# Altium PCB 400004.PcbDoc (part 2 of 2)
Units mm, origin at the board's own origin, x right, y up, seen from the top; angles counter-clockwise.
Board outline 80 x 40 mm, 4 copper layers (Top Layer, Mid-Layer 1, Mid-Layer 2, Bottom Layer), stack 1.582 mm thick; 116 components, 104 nets, 453 pads, 327 vias.
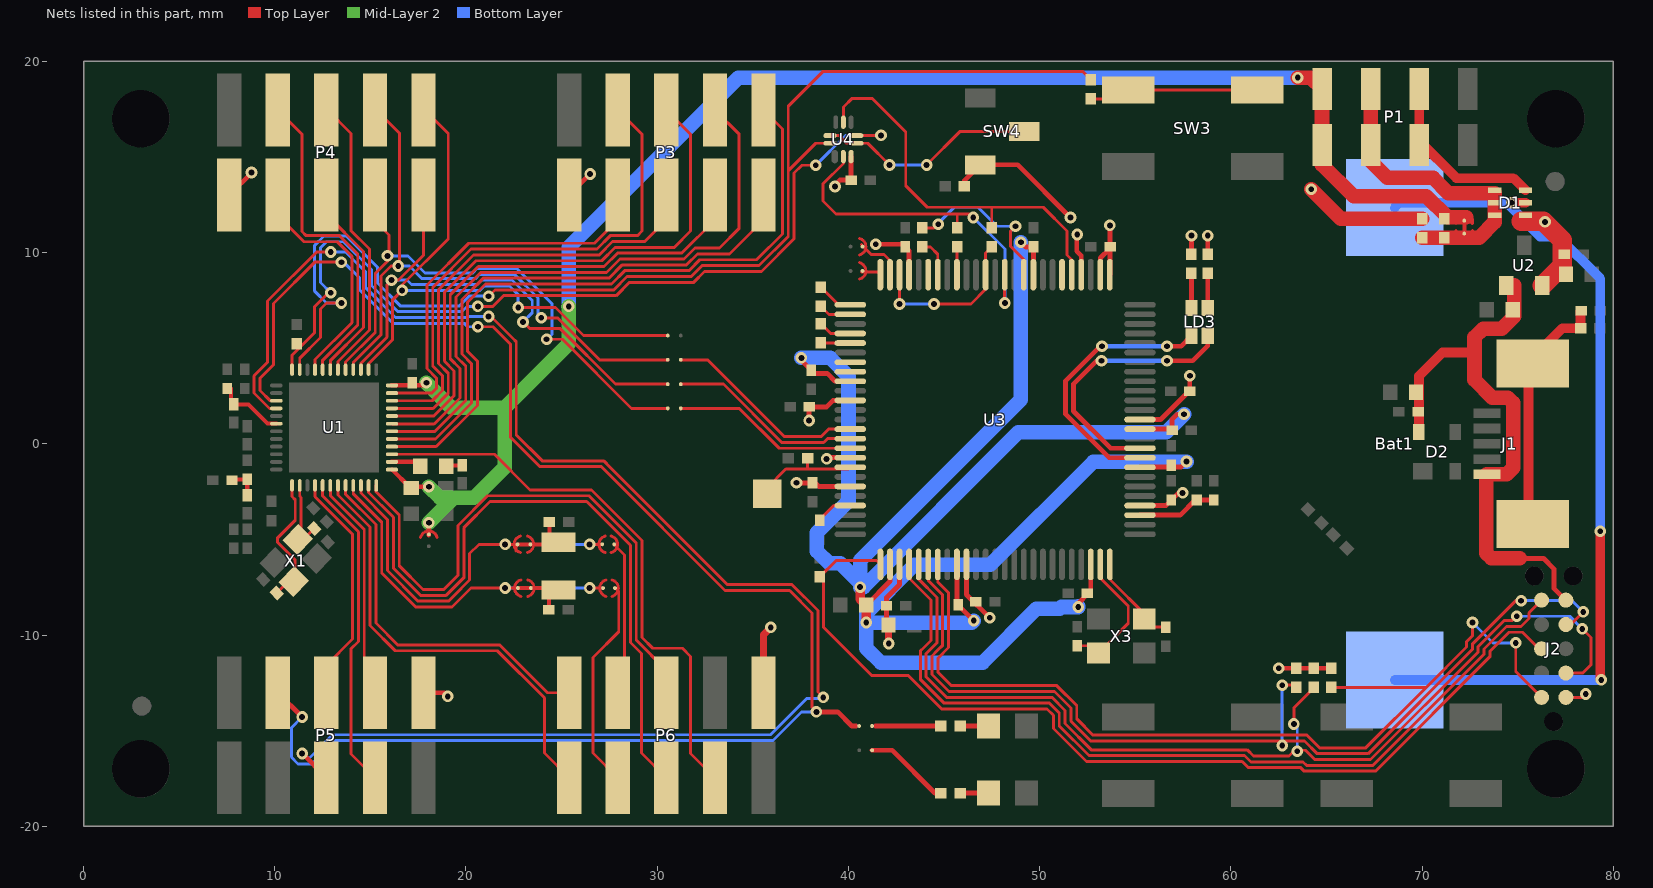
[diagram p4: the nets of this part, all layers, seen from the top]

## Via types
v1: diameter 0.61, hole 0.305, Top Layer to Bottom Layer, tented both sides, 311 vias
v2: diameter 0.66, hole 0.33, Top Layer to Bottom Layer, tented both sides, 16 vias

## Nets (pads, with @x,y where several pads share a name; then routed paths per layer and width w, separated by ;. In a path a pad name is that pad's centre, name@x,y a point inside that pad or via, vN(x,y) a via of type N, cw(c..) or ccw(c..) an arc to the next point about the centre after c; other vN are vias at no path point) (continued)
LED1: P5.4 SB7.1 U1.27 | length 86.3
  Top Layer w0.152: U1.27@10.106,2.253 9.761,2.253 9.223,2.791 9.223,3.429 9.931,4.137 9.931,7.339 12.092,9.5 v1(13.487,9.5) ; v1(20.625,6.121) 21.413,6.121 22.327,5.208 22.327,4.048 22.327,0.339 23.86,-1.194 27.077,-1.194 33.554,-7.671 36.93,-7.671 38.1,-8.841 38.1,-10.182 ; 38.1,-10.182 38.1,-13.792 v1(38.329,-14.021)
  Top Layer w0.254: P5.4@10.16,-13.018 v1(11.43,-14.287) ; v1(38.329,-14.021) 39.446,-14.021 40.183,-14.757 40.392,-14.757
  Bottom Layer w0.152: v1(11.43,-14.287) 10.871,-14.846 10.871,-16.388 11.222,-16.739 11.937,-16.739 13.156,-15.519 36.052,-15.519 37.55,-14.021 v1(38.329,-14.021) ; v1(13.487,9.5) 13.614,9.5 14.427,8.687 14.427,8.059 16.183,6.303 19.915,6.303 20.097,6.121 v1(20.625,6.121)
NetBat1_1: Bat1.1 D1.5 | length 45
  Top Layer w0.508: v1(74.691,12.609) D1.5@75.412,12.609 ; v1@79.324,-12.344 v1(79.324,-4.572)
  Bottom Layer w0.508: Bat1.1@68.572,-12.35 v1@79.324,-12.35 ; Bat1.1@68.572,12.35 68.831,12.609 74.412,12.609 76.175,10.846 77.114,10.846 79.324,8.636 v1(79.324,-4.572)
  other v1: 79.375,-12.344
NetC4_1: C4.1 C5.2 L3.1 | length 1.7
  Top Layer w0.229: C4.1@7.688,-1.864 C5.2@8.552,-1.864 ; L3.1@8.56,-2.685 C5.2@8.56,-1.856
NetC13_1: C13.1 SB2.1 X2.1 | length 2.6
  Top Layer w0.203: SB2.1@23.416,-7.544 23.503,-7.544 ; 23.568,-7.544 24.734,-7.544 24.341,-7.937 C13.1@24.341,-8.687
NetC14_1: C14.1 SB3.1 X2.2 | length 2.6
  Top Layer w0.203: SB3.1@23.391,-5.258 23.478,-5.258 ; 23.543,-5.258 24.734,-5.258 24.367,-4.89 C14.1@24.367,-4.089
NetC21_2: C21.2 J1.6 R9.2 | length 12.6
  Top Layer w0.508: J1.6@75.565,-3.965 75.565,3.965 J1.6@75.8,4.2 75.8,4.51 77.335,6.045 R9.2@78.291,6.045 C21.2@78.291,6.934
NetC31_2: C31.2 R12.2 U3.78 | length 4.1
  Top Layer w0.254: U3.78@55.251,-3.73 57.349,-3.73 58.141,-2.938 C31.2@59.03,-2.938
NetC32_2: C32.2 U3.47 | length 1.9
  Top Layer w0.152: C32.2@38.506,-3.962 39.239,-3.23 U3.47@40.101,-3.23
NetD1_6: D1.6 P1.3 | length 9.3
  Top Layer w0.508: P1.3@69.85,18.559 69.85,15.85 71.806,13.894 74.777,13.894 75.402,13.269 D1.6@75.412,13.269
NetL4_1: L4.1 U1.2 | length 1.6
  Top Layer w0.229: U1.2@16.106,-0.947 17.421,-0.947 L4.1@17.602,-1.128
NetL4_2: L4.2 L5.1 | length 0.8
  Top Layer w0.229: L4.2@18.982,-1.136 L5.1@19.786,-1.136
NetLD1_2: LD1.2 R5.1 | length 1.5
  Top Layer w0.254: R5.1@45.839,-18.263 LD1.2@47.327,-18.263
NetLD2_2: LD2.2 R6.1 | length 1.5
  Top Layer w0.254: R6.1@45.839,-14.757 LD2.2@47.327,-14.757
NetLD3_1: LD3.1 R23.1 | length 1.8
  Top Layer w0.254: LD3.1@58.794,7.1 R23.1@58.794,8.923
NetLD3_2: LD3.2 R22.1 | length 1.8
  Top Layer w0.254: LD3.2@57.944,7.1 R22.1@57.944,8.923
NetR3_1: R3.1 SW3.1 | length 8.9
  Top Layer w0.152: R3.1@52.68,18.042 53.653,18.042 54.121,18.51 SW3.1@61.389,18.51
NetR5_2: R5.2 SB6.2 | length 4.5
  Top Layer w0.254: SB6.2@41.239,-16.027 42.291,-16.027 44.526,-18.263 R5.2@44.839,-18.263
NetR6_2: R6.2 SB7.2 | length 3.4
  Top Layer w0.254: 41.411,-14.757 R6.2@44.839,-14.757
NetR18_2: R18.2 TP1.1 U3.43 | length 5.7
  Top Layer w0.152: TP1.1@35.763,-2.616 35.763,-2.286 36.728,-1.321 37.871,-1.321 ; R18.2@37.863,-0.762 37.863,-1.313 37.871,-1.321 ; U3.43@40.101,-1.23 40.01,-1.321 37.871,-1.321
NetSB17_1: SB17.1 U3.25 | length 1.1
  Top Layer w0.152: SB17.1@40.683,8.993 41.528,8.993 U3.25@41.676,8.845
NetSB18_1: SB18.1 U3.24 | length 2.6
  Top Layer w0.152: 40.682,10.414 41.197,9.899 41.867,9.899 42.176,9.589 U3.24@42.176,8.845
OB_LED1: LD3.4 U3.84 | length 14.1
  Top Layer w0.254: v1(53.264,5.105) 53.174,5.105 51.359,3.29 51.359,1.549 53.638,-0.73 U3.84@55.251,-0.73 ; v1(56.667,5.105) 57.399,5.105 LD3.4@57.944,5.65
  Bottom Layer w0.254: v1(53.264,5.105) v1(56.667,5.105)
OB_LED2: LD3.3 U3.85 | length 14.1
  Top Layer w0.254: v1(53.238,4.343) 52.987,4.343 51.765,3.122 51.765,1.718 53.713,-0.23 U3.85@55.251,-0.23 ; v1(56.667,4.343) 58.014,4.343 58.794,5.124 LD3.3@58.794,5.65
  Bottom Layer w0.254: v1(53.238,4.343) v1(56.667,4.343)
P0.00: P3.1 U1.4 | length 35.8
  Top Layer w0.152: U1.4@16.131,-0.147 18.442,-0.147 20.599,2.01 20.599,4.318 20.091,4.826 20.091,7.422 21.026,8.357 27.605,8.357 28.303,9.055 31.659,9.055 32.23,9.627 35.202,9.627 36.551,10.976 36.551,16.472 P3.1@35.56,17.463
P0.01: P3.2 U1.5 | length 29.4
  Top Layer w0.152: U1.5@16.131,0.253 18.411,0.253 20.295,2.137 20.295,4.192 19.787,4.7 19.787,7.548 20.9,8.661 27.478,8.661 28.177,9.36 31.533,9.36 32.104,9.931 33.782,9.931 35.56,11.709 P3.2@35.56,13.018
P0.02: P3.3 U1.6 | length 33.2
  Top Layer w0.152: U1.6@16.131,0.653 18.38,0.653 19.99,2.263 19.99,4.066 19.482,4.573 19.482,7.675 20.773,8.966 27.352,8.966 28.051,9.665 31.406,9.665 31.978,10.236 33.256,10.236 34.29,11.27 34.29,16.193 P3.3@33.02,17.463
P0.03: P3.4 U1.7 | length 26.5
  Top Layer w0.152: U1.7@16.131,1.053 16.143,1.041 18.337,1.041 19.685,2.389 19.685,3.939 19.177,4.447 19.177,7.801 20.647,9.271 27.226,9.271 27.924,9.97 31.28,9.97 33.02,11.709 P3.4@33.02,13.018
P0.04: P3.5 U1.8 | length 30.4
  Top Layer w0.152: U1.8@16.131,1.453 18.318,1.453 19.38,2.515 19.38,3.813 18.872,4.321 18.872,7.927 20.521,9.576 27.1,9.576 27.798,10.274 30.899,10.274 31.75,11.125 31.75,16.193 P3.5@30.48,17.463
P0.05: P3.6 U1.9 | length 23.6
  Top Layer w0.152: U1.9@16.131,1.853 18.287,1.853 19.075,2.642 19.075,3.687 18.567,4.195 18.567,8.053 20.395,9.881 26.973,9.881 27.672,10.579 29.35,10.579 30.48,11.709 P3.6@30.48,13.018
P0.06: P3.7 U1.10 | length 27.5
  Top Layer w0.152: U1.10@16.131,2.253 18.243,2.253 18.771,2.781 18.771,3.56 18.263,4.068 18.263,8.18 20.268,10.185 26.847,10.185 27.546,10.884 28.969,10.884 29.21,11.125 29.21,16.193 P3.7@27.94,17.463
P0.07: P3.8 U1.11 | length 20.8
  Top Layer w0.152: U1.11@16.106,2.653 18.212,2.653 18.466,2.907 18.466,3.434 17.958,3.942 17.958,8.306 20.142,10.49 26.721,10.49 27.94,11.709 P3.8@27.94,13.018
P0.08: P4.1 SB9.2 U1.14 | length 31.3
  Top Layer w0.152: U1.14@14.906,3.878 14.906,4.188 16.169,5.451 16.169,7.533 v1(16.662,8.026) 16.662,8.306 19.075,10.719 19.075,16.231 P4.1@17.805,17.501 ; v1(22.733,7.132) 24.676,7.132 26.146,5.662 SB9.2@30.557,5.662
  Bottom Layer w0.152: v1(16.662,8.026) 20.734,8.026 20.963,8.255 22.278,8.255 22.733,7.8 v1(22.733,7.132)
P0.09: P4.2 SB11.2 U1.15 | length 28.9
  Top Layer w0.152: U1.15@14.506,3.878 14.506,4.219 15.865,5.577 15.865,8.321 v1(16.104,8.56) 16.477,8.56 17.78,9.863 P4.2@17.78,13.018 ; v1(22.987,6.37) 23.317,6.04 24.906,6.04 27.824,3.122 SB11.2@30.557,3.122
  Bottom Layer w0.152: v1(16.104,8.56) 16.916,8.56 17.145,8.331 20.608,8.331 20.836,8.56 22.404,8.56 23.47,7.494 ; v1(22.987,6.37) 23.47,6.853 23.47,7.49
P0.10: P4.3 SB10.2 U1.16 | length 32.2
  Top Layer w0.152: U1.16@14.106,3.878 14.106,4.25 15.56,5.703 15.56,8.77 16.086,9.296 v1(16.459,9.296) 16.535,9.373 16.535,16.231 P4.3@15.265,17.501 ; v1(23.94,6.59) 24.787,6.59 26.985,4.392 SB10.2@30.557,4.392
  Bottom Layer w0.152: v1(16.459,9.296) 17.043,9.296 17.704,8.636 20.482,8.636 20.71,8.865 22.531,8.865 23.774,7.621 23.774,6.766 v1@23.94,6.6
P0.11: P4.4 SB12.2 U1.17 | length 29.8
  Top Layer w0.152: U1.17@13.706,3.878 13.706,4.281 15.255,5.829 15.255,8.905 v1@15.977,9.627 ; P4.4@15.24,13.018 15.24,11.659 15.977,10.922 v1@15.977,9.83 ; v1(24.22,5.47) 25.045,5.47 28.663,1.852 SB12.2@30.557,1.852
  Bottom Layer w0.152: v1(15.9,9.83) 16.967,9.83 17.856,8.941 20.355,8.941 20.584,9.169 22.657,9.169 24.5,7.326 24.5,5.72 v1@24.23,5.45
P0.12: P4.5 U1.18 | length 15.2
  Top Layer w0.152: P4.5@12.725,17.501 13.995,16.231 13.995,11.138 14.95,10.183 14.95,5.956 13.306,4.312 U1.18@13.306,3.878
P0.13: P4.6 U1.19 | length 10.7
  Top Layer w0.152: P4.6@12.725,13.056 12.725,11.977 14.645,10.057 14.645,6.082 12.906,4.343 U1.19@12.906,3.878
P0.14: P4.7 U1.20 | length 17.1
  Top Layer w0.152: P4.7@10.16,17.463 11.43,16.193 11.43,11.1 11.646,10.884 13.387,10.884 14.341,9.931 14.341,6.208 12.506,4.374 U1.20@12.506,3.878
P0.15: P4.8 U1.21 | length 12.6
  Top Layer w0.152: P4.8@10.16,13.018 10.16,11.939 11.532,10.566 13.274,10.566 14.036,9.804 14.036,6.334 12.106,4.405 U1.21@12.106,3.878
P0.20: P5.5 U1.28 | length 82.7
  Top Layer w0.152: U1.28@10.106,1.853 9.73,1.853 8.918,2.665 8.918,3.555 9.627,4.263 9.627,7.465 12.194,10.033 v1(12.929,10.033) ; v1(21.184,6.655) 21.311,6.655 22.427,5.538 22.631,5.334 22.631,3.922 22.631,0.466 23.986,-0.889 27.203,-0.889 27.546,-1.232 33.68,-7.366 37.056,-7.366 38.405,-8.714 38.405,-12.979 v1(38.684,-13.259)
  Top Layer w0.254: v1(11.43,-16.192) P5.5@12.7,-17.462
  Bottom Layer w0.152: v1(11.43,-16.192) 11.671,-16.434 11.811,-16.434 13.03,-15.215 35.926,-15.215 37.831,-13.31 38.633,-13.31 v1(38.684,-13.259) ; v1(12.929,10.033) 13.708,10.033 14.757,8.984 14.757,8.159 16.309,6.608 20.095,6.608 20.142,6.655 v1(21.184,6.655)
P0.21: P5.6 U1.40 | length 12.3
  Top Layer w0.152: U1.40@12.106,-2.147 12.106,-2.764 14.072,-4.729 14.072,-10.212 12.7,-11.583 P5.6@12.7,-13.018
P0.22: P5.7 U1.41 | length 16.8
  Top Layer w0.152: U1.41@12.506,-2.147 12.506,-2.733 14.376,-4.603 14.376,-10.338 13.995,-10.719 13.995,-16.218 P5.7@15.24,-17.462
P0.23: P5.8 U1.42 | length 11.8
  Top Layer w0.152: U1.42@12.906,-2.147 12.906,-2.702 14.681,-4.477 14.681,-12.459 P5.8@15.24,-13.018
P0.24: P6.1 U1.43 | length 23.4
  Top Layer w0.152: U1.43@13.306,-2.147 13.306,-2.671 14.986,-4.351 14.986,-9.5 16.307,-10.82 21.641,-10.82 24.105,-13.284 24.105,-16.167 P6.1@25.4,-17.462
P0.25: P6.2 U1.44 | length 19.5
  Top Layer w0.152: U1.44@13.706,-2.147 13.706,-2.64 15.291,-4.224 15.291,-9.373 16.433,-10.516 21.767,-10.516 24.269,-13.018 P6.2@25.4,-13.018
P0.26: P6.3 SB4.2 | length 11.1
  Top Layer w0.152: SB4.2@27.78,-7.544 27.8,-7.544 27.991,-7.735 27.991,-9.83 26.645,-11.176 26.645,-16.167 P6.3@27.94,-17.462
P0.27: P6.4 SB5.2 | length 8.3
  Top Layer w0.152: 27.911,-5.258 27.737,-5.258 28.296,-5.817 28.296,-12.662 P6.4@27.94,-13.018
P0.28: P6.5 U1.47 | length 35.3
  Top Layer w0.152: U1.47@14.906,-2.147 14.906,-2.547 16.205,-3.846 16.205,-6.505 17.625,-7.925 18.967,-7.925 19.888,-7.003 19.888,-4.394 21.26,-3.023 26.315,-3.023 28.6,-5.308 28.6,-10.389 29.185,-10.973 29.185,-16.167 P6.5@30.48,-17.462
P0.29: P6.6 U1.48 | length 30.7
  Top Layer w0.152: U1.48@15.306,-2.147 15.306,-2.516 16.51,-3.719 16.51,-6.379 17.751,-7.62 18.84,-7.62 19.583,-6.877 19.583,-4.268 21.134,-2.718 26.441,-2.718 27.038,-3.315 28.905,-5.182 28.905,-10.262 30.48,-11.837 P6.6@30.48,-13.018
P0.30: P6.7 U1.3 | length 29.8
  Top Layer w0.152: U1.3@16.131,-0.547 21.488,-0.547 23.355,-2.413 26.568,-2.413 29.21,-5.055 29.21,-10.136 29.767,-10.693 31.318,-10.693 31.75,-11.125 31.75,-16.192 P6.7@33.02,-17.462
RESET: J2.10 R21.1 U3.57 | length 50.5
  Top Layer w0.152: U3.57@44.676,-6.305 44.676,-7.224 45.237,-7.786 45.237,-10.66 44.696,-11.201 44.696,-11.243 44.679,-11.26 44.679,-11.938 45.39,-12.649 50.9,-12.649 51.943,-13.692 51.943,-14.379 52.8,-15.237 63.979,-15.237 64.642,-15.9 67.059,-15.9 70.217,-12.743 ; R21.1@65.253,-12.743 70.217,-12.743 ; v1(72.644,-9.347) 72.644,-10.036 72.328,-10.352 72.328,-10.631 70.217,-12.743 ; v1(74.905,-10.412) 74.905,-11.913 J2.10@76.251,-13.259
  Bottom Layer w0.152: v1(72.644,-9.347) 73.709,-10.412 v1(74.905,-10.412)
RTCKIN: U3.6
RTS: SB10.1 U3.39 | length 10.7
  Top Layer w0.152: SB10.1@31.233,4.392 32.631,4.392 36.644,0.38 38.582,0.38 38.972,0.77 U3.39@40.101,0.77
RXD: SB11.1 U3.40 | length 10.2
  Top Layer w0.152: SB11.1@31.233,3.122 33.468,3.122 36.515,0.075 38.708,0.075 38.903,0.27 U3.40@40.101,0.27
RXDAUX: U3.32
SW_EN: SW4.2 U4.4 U4.9 | length 11.5
  Top Layer w0.152: U4.9@39.04,16.12 39.51,16.12 39.91,15.72 U4.4@40.44,15.72 41.01,15.72 v1(42.15,14.58) ; v1(44.09,14.58) 45.851,16.341 SW4.2@49.193,16.341
  Bottom Layer w0.152: v1(42.15,14.58) v1(44.09,14.58)
SWCLK: R1.2 U1.24 U4.5 | length 46
  Top Layer w0.152: U1.24@10.906,3.878 10.906,4.633 12.09,5.817 12.09,7.18 12.81,7.899 v1(12.929,7.899) ; v1(20.625,7.188) 21.405,7.188 21.963,7.747 27.857,7.747 28.556,8.446 31.911,8.446 32.483,9.017 35.454,9.017 37.16,10.723 37.16,14.159 37.571,14.57 v1(38.29,14.57) ; U4.5@40.44,16.12 41.7,16.12 v1(41.71,16.13)
  Bottom Layer w0.152: v1(12.929,7.899) 12.395,8.433 12.395,10.254 12.708,10.566 13.606,10.566 15.062,9.11 15.062,8.286 16.435,6.913 19.787,6.913 20.062,7.188 v1(20.625,7.188) ; v1(38.29,14.57) 39.85,16.13 v1(41.71,16.13)
SWDIO: R3.2 U1.23 U4.10 | length 63.8
  Top Layer w0.152: U1.23@11.306,3.878 11.306,4.473 12.395,5.562 12.395,7.054 12.708,7.366 v1(13.487,7.366) ; v1@21.31,7.722 v1(21.184,7.722) 21.514,8.052 27.731,8.052 28.429,8.75 31.785,8.75 32.357,9.322 35.328,9.322 36.855,10.849 36.855,13.535 36.855,14.285 ; U4.10@39.04,15.72 38.29,15.72 36.855,14.285 ; R3.2@52.68,19.042 52.24,19.482 38.684,19.482 36.855,17.653 36.855,14.285
  Bottom Layer w0.152: v1(13.487,7.366) 12.708,7.366 12.09,7.983 12.09,10.38 12.581,10.871 13.732,10.871 15.367,9.236 15.367,8.412 16.561,7.217 19.66,7.217 20.165,7.722 v1(21.184,7.722)
T_RESET: R17.2 U3.29 | length 1.8
  Top Layer w0.152: R17.2@38.557,6.291 39.078,5.77 U3.29@40.101,5.77
T_TDI: R14.2 U3.10 | length 8.8
  Top Layer w0.152: R14.2@43.866,11.295 44.467,11.295 44.704,11.532 v1(44.704,11.481) ; v1(48.743,11.379) 48.481,11.117 48.481,10.328 49.176,9.633 U3.10@49.176,8.845
  Bottom Layer w0.152: v1(44.704,11.481) 44.704,11.532 45.542,12.37 46.787,12.37 47.777,11.379 v1(48.743,11.379)
T_TDO: U3.20
T_TRST: R13.2 U3.26 | length 1.9
  Top Layer w0.152: R13.2@38.557,8.196 39.483,7.27 U3.26@40.101,7.27
TCKIN: R16.2 U3.5 U4.7 | length 20.6
  Top Layer w0.152: U4.7@39.74,16.82 39.74,17.61 40.2,18.07 41.23,18.07 43,16.3 43,13.5 44.13,12.37 47.498,12.37 ; R16.2@47.498,11.295 47.498,12.37 ; U3.5@51.676,8.845 51.676,9.64 51.435,9.881 51.435,11.125 50.19,12.37 47.498,12.37
TCKOUT: R16.1 U3.14 U3.23 | length 8.7
  Top Layer w0.152: v1(42.672,7.315) 42.672,8.841 U3.23@42.676,8.845 ; v1(44.475,7.315) 46.406,7.315 47.176,8.085 U3.14@47.176,8.845 47.176,9.973 R16.1@47.498,10.295
  Bottom Layer w0.152: v1(42.672,7.315) v1(44.475,7.315)
TCKS: J2.4 R24.1 U3.56 | length 51.3
  Top Layer w0.152: U3.56@44.176,-6.305 44.176,-7.155 44.933,-7.912 44.933,-10.533 44.653,-10.813 44.374,-11.092 44.374,-12.064 45.264,-12.954 50.774,-12.954 51.638,-13.818 51.638,-14.506 52.674,-15.542 63.852,-15.542 64.516,-16.205 67.185,-16.205 72.633,-10.758 72.633,-10.478 74.907,-8.204 v1(75.184,-8.204) ; v1(62.687,-12.624) 63.305,-12.624 R24.1@63.424,-12.743 ; J2.4@77.521,-9.449 77.775,-9.449 v1(78.435,-8.788)
  Bottom Layer w0.152: v1@62.687,-15.748 v1(62.687,-12.624) ; v1(75.184,-8.204) 77.851,-8.204 v1(78.435,-8.788)
  other v1: 62.687,-15.773
TDIOUT: R14.1 U3.19 | length 2
  Top Layer w0.152: R14.1@43.866,10.295 44.29,10.295 44.676,9.909 U3.19@44.676,8.845
TDIS: J2.8 R19.1 U3.51 | length 50.9
  Top Layer w0.152: U3.51@41.676,-6.305 41.467,-6.096 39.362,-6.096 R19.1@38.506,-6.952 38.71,-7.155 38.71,-9.601 41.224,-12.116 43.132,-12.116 44.885,-13.868 50.394,-13.868 50.724,-14.199 50.724,-14.884 52.451,-16.612 60.596,-16.612 60.923,-16.939 63.657,-16.939 63.838,-17.12 67.564,-17.12 73.547,-11.136 73.547,-10.857 74.549,-9.855 75.26,-9.855 76.124,-10.719 J2.8@76.251,-10.719
TDOS: J2.6 U3.54 | length 45.4
  Top Layer w0.152: U3.54@43.176,-6.305 43.176,-7.017 44.323,-8.165 44.323,-10.279 43.976,-10.626 43.976,-10.628 43.764,-10.84 43.764,-12.317 45.011,-13.564 50.52,-13.564 51.029,-14.072 51.029,-14.758 52.577,-16.307 60.722,-16.307 61.049,-16.634 63.783,-16.634 63.964,-16.815 67.438,-16.815 73.242,-11.01 73.242,-10.731 74.423,-9.55 75.176,-9.55 75.59,-9.136 75.59,-8.839 J2.6@76.251,-8.179
TMSIN: R15.2 U3.12 U4.2 | length 18.3
  Top Layer w0.152: U4.2@39.74,15.02 39.74,14.66 38.68,13.6 38.68,12.7 39.359,12.021 45.695,12.021 ; R15.2@45.695,11.295 45.695,12.021 ; v1(46.533,11.836) 46.348,12.021 45.695,12.021 ; U3.12@48.176,8.845 48.176,7.374 v1(48.184,7.366)
  Bottom Layer w0.152: v1(46.533,11.836) 48.184,10.185 v1(48.184,7.366)
TMSOUT: R15.1 U3.17 | length 1.4
  Top Layer w0.152: U3.17@45.676,8.845 R15.1@45.676,10.276
TMSS: J2.2 R20.1 U3.55 | length 54.4
  Top Layer w0.152: U3.55@43.676,-6.305 43.676,-7.086 44.628,-8.038 44.628,-10.407 44.32,-10.715 44.069,-10.966 44.069,-12.191 45.137,-13.259 50.648,-13.259 51.333,-13.945 51.333,-14.632 52.704,-16.002 60.858,-16.002 61.185,-16.329 63.046,-16.329 63.348,-16.027 63.906,-16.027 64.389,-16.51 67.311,-16.51 72.938,-10.884 72.938,-10.604 74.296,-9.246 74.727,-9.246 v1(74.955,-9.017) ; v1@63.297,-14.681 63.297,-13.809 R20.1@64.338,-12.768 ; J2.2@77.521,-11.989 78.41,-11.989 78.842,-11.557 78.842,-10.135 v1(78.384,-9.677)
  Bottom Layer w0.152: v1(63.297,-14.656) 63.475,-14.834 v1@63.475,-16.231 ; v1(74.955,-9.017) 77.724,-9.017 v1(78.384,-9.677) v1@78.41,-9.703
  other v1: 63.475,-16.078
TRESOUT: R17.1 U3.30 | length 1.5
  Top Layer w0.152: R17.1@38.583,5.27 U3.30@40.101,5.27
TRSTOUT: R13.1 U3.27 | length 1.7
  Top Layer w0.152: R13.1@38.557,7.196 38.983,6.77 U3.27@40.101,6.77
TXD: SB12.1 U3.41 | length 9.7
  Top Layer w0.152: SB12.1@31.233,1.852 34.298,1.852 36.38,-0.23 U3.41@40.101,-0.23
TXDAUX: U3.33
V3: D1.1 D1.2 D1.3 P1.2 R4.2 R8.1 SB8.1 | length 16.6
  Top Layer w0.762: P1.2@67.31,18.559 P1.2@67.31,15.629 67.31,14.783 68.186,13.907 70.574,13.907 71.374,13.106 73.812,13.106 D1.2@73.812,12.609 D1.3@73.812,11.959 73.812,11.602 72.988,10.778 R8.1@70.002,10.778
V5: C16.2 C22.2 C23.2 D2.4 J1.1 J2.5 U2.1 | length 30
  Top Layer w0.254: 75.108,-5.994 76.352,-5.994 76.911,-6.553 76.911,-7.569 J2.5@77.521,-8.179
  Top Layer w0.508: D2.4@69.84,0.619 69.84,3.546 71.069,4.775 72.746,4.775
  Top Layer w0.762: 74.828,8.28 74.828,6.68 74.168,6.02 73.203,6.02 72.746,5.563 72.746,3.35 73.679,2.417 74.495,2.417 74.778,2.134 74.778,-1.245 74.422,-1.6 J1.1@73.4,-1.6 73.367,-1.633 73.367,-5.726 73.635,-5.994 75.108,-5.994
VCC3: C17.2 C18.2 C28.2 C29.2 C30.2 C33.2 C34.2 C35.2 C36.2 C37.2 C38.2 D1.4 J2.1 R2.2 R20.2 R21.2 R22.2 R23.2 R24.2 SW4.1 U2.2 U3.1 U3.2 U3.4 U3.22 U3.36 U3.42 U3.45 U3.53 U3.60 U3.79 U3.88 | length 49.5
  Top Layer w0.152: J2.1@77.521,-13.259 78.384,-13.259 v1(78.562,-13.081)
  Top Layer w0.254: v1@37.168,-2.04 C36.2@38.125,-2.04 38.26,-2.04 38.45,-2.23 U3.45@40.101,-2.23 ; v1(37.948,1.219) 37.948,1.913 C35.2@37.965,1.93 38.862,1.93 39.202,2.27 U3.36@40.101,2.27 ; v1@38.862,-0.711 40.082,-0.711 U3.42@40.101,-0.73 ; v1(41.427,10.439) 42.832,10.439 C34.2@42.977,10.295 43.176,10.096 U3.22@43.176,8.845 ; C29.2@42.099,-9.474 41.994,-9.37 C28.2@41.994,-8.458 41.994,-8.044 42.676,-7.362 U3.53@42.676,-6.305 ; R2.2@46.07,13.46 46.07,13.768 SW4.1@46.893,14.591 48.858,14.591 v1(51.613,11.836) ; U3.60@46.176,-6.305 46.176,-7.89 v1@47.388,-9.102 ; v1@51.943,10.947 51.943,10.072 52.176,9.84 U3.4@52.176,8.845 ; U3.2@53.176,8.845 53.176,9.716 C33.2@53.67,10.211 ; U3.1@53.676,8.845 v1(53.676,11.424) ; U3.79@55.251,-3.23 56.604,-3.23 C30.2@56.888,-2.946 ; U3.88@55.251,1.27 56.337,1.27 C38.2@57.777,2.71 ; C30.2@56.896,-2.938 57.269,-2.565 v1(57.48,-2.565) v1@57.506,-2.565 ; C38.2@57.853,2.743 v1@57.853,3.556 ; R22.2@57.944,9.923 v1(57.944,10.889) ; R23.2@58.794,9.923 v1(58.794,10.889) ; v1(62.509,-11.735) 65.245,-11.735 R21.2@65.253,-11.743
  Top Layer w0.381: C29.2@42.099,-9.474 42.099,-10.425 v1(42.113,-10.439)
  Top Layer w1.016: 75.184,11.633 76.352,11.633 77.343,10.643 77.343,9.327 U2.2@76.297,8.28
  other v1: 47.396,-9.093 37.287,-2.032 38.862,-0.787 57.861,3.556 51.968,10.947 76.429,11.608
VCC_IO: C19.2 P3.10 P4.10 P5.10 P6.10 R8.2 U4.3 | length 17.9
  Top Layer w0.254: P4.10@7.62,13.018 v1(8.788,14.186) ; P5.10@17.78,-13.018 v1@18.885,-13.018 ; P3.10@25.4,13.018 v1@26.511,14.129 ; v1@39.22,13.46 39.55,13.79 40.14,13.79 U4.3@40.14,15.03
  Top Layer w0.381: P6.10@35.56,-14.249 P6.10@35.56,-13.018 35.56,-9.982 v1(35.941,-9.601)
  Top Layer w0.762: v1(64.211,13.31) 65.743,11.778 R8.2@70.002,11.778
  other v1: 19.05,-13.208 39.3,13.46 26.492,14.11
VCC_NRF: C7.1 C11.1 P1.1 R4.1 SB1.1 SB8.2 U1.1 U1.12 | length 85.7
  Top Layer w0.152: 72.309,11.842 72.314,11.837 72.643,11.514 72.643,11.743
  Top Layer w0.229: U1.12@16.106,3.053 17.796,3.053 v1(17.932,3.19) ; U1.1@16.131,-1.347 17.03,-2.245 v1(18.059,-2.245) ; SB1.1@18.059,-4.775 v1(18.059,-4.125)
  Top Layer w0.762: v1(63.5,19.152) 64.178,19.152 P1.1@64.77,18.559 P1.1@64.77,15.629 64.77,14.605 66.421,12.954 70.231,12.954 71.343,11.842 72.135,11.842 72.289,11.842 72.309,11.842
  Mid-Layer 2 w0.762: v1(17.932,3.19) 19.23,1.892 22.034,1.892 ; v1(18.059,-4.125) 19.355,-2.83 ; v1(18.059,-2.245) 18.644,-2.83 19.355,-2.83 ; v1(25.375,7.188) 25.375,5.232 22.034,1.892 ; 19.355,-2.83 20.437,-2.83 22.034,-1.232 22.034,1.892
  Bottom Layer w0.762: v1(25.375,7.188) 25.375,10.287 34.239,19.152 v1(63.5,19.152)
VCORE: C26.1 C27.2 C39.2 C40.2 C41.2 C42.2 C43.2 U3.9 U3.34 U3.52 U3.59 U3.73 U3.83 U3.87 | length 119
  Top Layer w0.254: v1@37.414,4.496 38.067,3.843 C40.2@38.067,3.683 ; C40.2@38.092,3.683 38.887,3.683 39.3,3.27 U3.34@40.101,3.27 ; C27.2@40.934,-8.433 42.176,-7.191 U3.52@42.176,-6.305 ; U3.59@45.676,-6.305 45.676,-8.363 v1(46.558,-9.246) ; v1(49.022,10.541) 49.275,10.288 C39.2@49.676,10.288 ; U3.9@49.676,8.845 C39.2@49.676,10.27 ; v1@52.037,-8.331 52.518,-7.847 52.679,-7.686 U3.73@52.676,-6.305 ; U3.87@55.251,0.77 C43.2@56.76,0.77 ; U3.83@55.262,-1.219 57.392,-1.219 v1(57.683,-0.928) ; C43.2@56.929,0.711 56.929,1.281 57.198,1.549 v1(57.556,1.549)
  Top Layer w0.508: v1@40.615,-7.518 40.615,-8.113 C27.2@40.934,-8.433 v1(40.934,-9.347)
  Bottom Layer w0.762: v1(37.541,4.496) 39.04,4.496 40.005,3.531 40.005,-3.001 38.354,-4.652 38.354,-5.605 38.997,-6.248 39.565,-6.248 v1@40.615,-7.298 ; v1(46.558,-9.246) 46.457,-9.347 v1(40.934,-9.347) ; v1(49.022,10.541) 49.022,2.311 40.615,-6.096 v1@40.615,-7.298 ; v1@52.019,-8.509 v1(52.019,-8.534) 51.147,-8.534 51.046,-8.636 49.835,-8.636 47.015,-11.455 41.707,-11.455 40.934,-10.683 v1(40.934,-9.347) ; v1(57.556,1.549) 56.617,0.61 48.895,0.61 40.792,-7.493 v1(40.615,-7.493) v1@40.615,-7.298 ; v1(57.683,-0.928) 52.819,-0.928 47.422,-6.325 43.459,-6.325 40.934,-8.85 v1(40.934,-9.347)
VDD_PA: C3.1 L2.1 U1.30 | length 3.6
  Top Layer w0.203: C3.1@7.722,2.893 7.722,2.192 L2.1@7.849,2.065 8.62,2.065 9.632,1.053 U1.30@10.106,1.053
XC1: C1.1 U1.37 X1.1 | length 7.1
  Top Layer w0.152: C1.1@10.107,-7.806 11.049,-6.864 11.049,-6.055 10.135,-5.141 ; U1.37@10.906,-2.172 10.906,-2.762 11.071,-2.927 11.071,-4.001 10.135,-4.938 ; 10.135,-5.141 10.135,-4.938 ; 10.135,-5.141 10.135,-4.938
XC2: C2.1 U1.38 X1.3 | length 4
  Top Layer w0.152: X1.3@11.206,-5.01 X1.3@11.306,-4.91 ; U1.38@11.306,-2.147 U1.38@11.306,-2.172 11.306,-2.731 11.376,-2.801 11.376,-4.84 X1.3@11.306,-4.91 ; C2.1@12.067,-4.432 11.536,-4.963 11.306,-4.963 X1.3@11.306,-4.91
XIN: C24.1 U3.75 X3.3 | length 5.1
  Top Layer w0.152: U3.75@53.676,-6.305 53.676,-7.092 55.577,-8.993 X3.3@55.678,-8.993 ; X3.3@55.246,-9.171 X3.3@55.474,-9.171 55.887,-9.584 C24.1@56.591,-9.584
XL1: SB3.2 SB5.1 U1.46 | length 20
  Top Layer w0.152: U1.46@14.506,-2.147 14.506,-2.578 15.9,-3.972 15.9,-6.632 17.498,-8.23 19.093,-8.23 19.355,-7.968 20.193,-7.13 20.193,-5.74 20.676,-5.258 v1(22.047,-5.258) 22.621,-5.258 22.621,-5.595 ; v1(26.467,-5.258) SB5.1@27.127,-5.258
  Top Layer w0.203: SB3.2@22.701,-5.258 22.801,-5.258
  Bottom Layer w0.152: v1(22.047,-5.258) v1(26.467,-5.258)
XL2: SB2.2 SB4.1 U1.45 | length 18.5
  Top Layer w0.152: U1.45@14.106,-2.147 14.106,-2.609 15.596,-4.098 15.596,-6.758 17.372,-8.534 19.272,-8.534 20.263,-7.544 v1(22.047,-7.544) SB2.2@22.646,-7.544 ; v1(26.467,-7.544) SB4.1@27.17,-7.544
  Bottom Layer w0.152: v1(22.047,-7.544) v1(26.467,-7.544)
XOUT: C25.1 U3.74 X3.1 | length 7.2
  Top Layer w0.152: C25.1@51.968,-10.558 52.695,-10.558 X3.1@53.086,-10.949 53.086,-10.935 54.635,-9.385 54.635,-8.484 53.176,-7.024 U3.74@53.176,-6.305
pads on no net: Bat1.2 Fid1.0 Fid2.0 H1. H2. H3. H4. J1.4 J2.0 J2.7 J2.9 P6.8 U3.7 U3.8 U3.11 U3.13 U3.15 U3.16 U3.18 U3.28 U3.31 U3.37 U3.44 U3.48 U3.49 U3.50 U3.58 U3.62 U3.63 U3.64 U3.65 U3.66 U3.67 U3.68 U3.69 U3.70 U3.71 U3.86 U3.90 U3.91 U3.92 U3.93 U3.94 U3.95 U3.96 U3.97 U3.98 U3.100 U4.1 U4.6

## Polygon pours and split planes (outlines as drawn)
GND on Top Layer "Top_Layer-GND" (solid, remove dead copper, pour order 8): -0.584,-20.574 -0.584,20.469 -0.419,20.708 80.204,20.708 80.41,21.006 80.41,-20.455 80.493,-20.574
VCC3 on Mid-Layer 2 "Mid_Layer_2-VCC3" (solid, remove dead copper, pour order 10): 36.373,-14.148 36.373,12.027 36.462,12.18 80.133,12.18 80.245,12.37 80.245,-14.072 80.289,-14.148
VCC_IO on Mid-Layer 2 "Mid_Layer_2-VCC_IO" (solid, remove dead copper, pour order 9): -2.381,-21.006 -2.381,20.47 -2.209,20.711 81.64,20.711 81.855,21.013 81.855,-20.885 81.94,-21.006
GND on Bottom Layer "Bottom_Layer-GND" (solid, remove dead copper, pour order 6): -0.559,-20.904 -0.559,20.414 -0.393,20.655 80.635,20.655 80.842,20.955 80.842,-20.784 80.924,-20.904
GND on Mid-Layer 1 "Mid_Layer_1-GND" (solid, remove dead copper, pour order 7): -0.827,-20.075 -0.827,20.968 -0.662,21.206 79.961,21.206 80.167,21.504 80.167,-19.956 80.25,-20.075

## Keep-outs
Keep-Out Layer:
  the board outline again, w0.152

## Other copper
Top Layer:
  pour cut-out: 6.223,-3.541 8.509,-3.541 8.509,-5.141 6.223,-5.141
  pour cut-out: 6.375,-2.271 9.931,-2.271 9.931,-3.871 6.375,-3.871
  pour cut-out: 6.934,3.571 9.525,3.571 9.525,-2.957 6.934,-2.957
  pour cut-out: 6.604,20.244 -0.251,20.244 -0.217,-20.32 6.6,-20.32
  pour cut-out: 10.617,3.393 15.596,3.393 15.596,-1.636 10.618,-1.636
  pour cut-out: 11.746,-3.755 12.421,-3.079 12.978,-3.636 12.302,-4.312
  pour cut-out: 7.417,-12.141 7.417,-10.871 5.944,-10.871 5.944,-12.141
  region net GND: 72.885,1.346 72.885,1.308 72.339,1.308 72.196,1.309 72.098,2.134 72.644,2.553 73.381,1.803
  pour cut-out: 69.85,-2.508 69.85,-1.238 68.377,-1.238 68.377,-2.508
  pour cut-out: 10.744,14.63 10.744,15.9 9.271,15.9 9.271,14.63
  pour cut-out: 28.55,14.681 28.55,15.951 27.076,15.951 27.076,14.681
  pour cut-out: 16.104,-15.875 16.104,-14.605 14.63,-14.605 14.63,-15.875
Mid-Layer 1:
  pour cut-out: 6.934,3.571 9.525,3.571 9.525,-4.572 6.934,-4.572
  pour cut-out: 6.604,20.244 -0.251,20.244 -0.217,-20.32 6.6,-20.32
  pour cut-out: 21.898,-4.275 24.079,-4.275 24.079,-8.865 21.898,-8.865
  pour cut-out: 39.776,-13.047 41.958,-13.047 41.958,-17.636 39.776,-17.636
  pour cut-out: 71.275,13.554 73.457,13.554 73.457,8.964 71.275,8.964
  pour cut-out: 29.765,7.374 32.1,7.374 32.1,0.42 29.765,0.42
Mid-Layer 2:
  pour cut-out: 6.934,3.571 9.525,3.571 9.525,-4.572 6.934,-4.572
  pour cut-out: 6.604,20.244 -0.251,20.244 -0.217,-20.32 6.6,-20.32
Bottom Layer:
  pour cut-out: 6.604,20.168 -0.251,20.168 -0.217,-20.32 6.6,-20.32

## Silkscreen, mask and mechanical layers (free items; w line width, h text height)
Top Overlay:
  region: 61.723,8.99 61.723,7.544 62.265,8.267
  lines w0.152: 68.58,12.573 68.58,19.736
  lines w0.2: 21.311,1.777 ccw(c22.311,1.777) 22.311,0.777 27.311,0.777 ccw(c27.311,1.777) 28.311,1.777 28.311,6.777 ccw(c27.311,6.777) 27.311,7.777 22.311,7.777 ccw(c22.311,6.777) 21.311,6.777 21.311,1.777
  lines w0.203: 61.415,6.556 ccw(c61.618,6.556) 61.618,6.353 69.035,6.353 ccw(c69.035,6.556) 69.238,6.556 ; 61.415,6.558 61.415,9.967 ; 61.415,9.985 cw(c61.618,9.985) 61.618,10.188 69.035,10.188 cw(c69.035,9.985) 69.238,9.985 ; 69.238,6.558 69.238,9.967
  lines w0.279: 61.864,9.599 62.867,8.262 61.869,6.931 ; 62.584,6.933 63.417,8.016 68.758,8.016 ; 62.592,9.598 63.418,8.524 68.758,8.524
  text "GND" at 6.604,19.25 h0.89 r180
  text "GND" at 24.384,19.25 h0.89 r180
  text "OFF" at 49.63,17.68 h0.89
  text "J-Link" at 41.96,16.567 h1.02
  text "OB" at 43.154,15.17 h1.02
  text "ON" at 49.55,14.13 h0.89
  text "+" at 69.215,12.7 h1.52
  text "-" at 71.806,12.7 h1.52
  text "nRF current" at 62.281,12.548 h1.52
  text "VCC" at 6.604,12.14 h0.89 r180
  text "VCC" at 24.384,12.14 h0.89 r180
  text "nRF_RESET" at 54.331,11.938 h1.02
  text "measurement" at 62.205,11.608 h1.52
  text "P0.08-P0.15" at 17.5,10.541 h1.14 r180
  text "P0.00-P0.07" at 35.65,10.541 h1.14 r180
  text "S" at 63.551,6.774 h1.35
  text "E" at 64.441,6.774 h1.35
  text "G" at 65.225,6.774 h1.35
  text "G" at 66.215,6.774 h1.35
  text "E" at 67.239,6.774 h1.35
  text "R" at 68.075,6.774 h1.35
  text "TM" at 63.337,5.337 h0.94
  text "J-Link" at 59.868,4.915 h1.45
  text "Technology" at 64.62,4.915 h1.45
  text "LABEL" at 22.53,3.8 h1.02
  text "www.segger.com" at 59.949,3.764 h1.68
  text "SEMICONDUCTOR" at 0.895,2.853 h1.65 r270
  text "NORDIC" at 2.386,2.767 h3.81 r270
  text "XTAL" at 22.454,-0.787 h1.14 r270
  text "GPIO" at 26.899,-1.092 h1.14 r270
  text "400004" at 78.346,-8.141 h2.03 r270
  text "P0.16-P0.23" at 7.899,-10.617 h1.14
  text "P0.24-P0.31" at 25.73,-10.617 h1.14
  text "VCC" at 18.796,-12.14 h0.89
  text "VCC" at 36.576,-12.14 h0.89
  text "Button 1" at 66.345,-12.878 h1.14
  text "Button 0" at 54.712,-12.929 h1.14
  text "LED 1" at 46.736,-13.665 h1.14
  text "0101RUBR" at 78.943,-14.148 h0.64 r270
  text "LED 0" at 46.533,-17.17 h1.14
  text "GND" at 18.796,-19.25 h0.89
  text "GND" at 36.576,-19.25 h0.89
Bottom Overlay:
  drawing of 168 lines, arcs and shapes, not listed
  text "HW" at 22.32,12.155 h2.4 r270
  text "RTS" at 34.77,12.066 h2.2 r270
  text "CTS" at 40.99,12.016 h2.2 r270
  text "TXD" at 31.67,11.946 h2.2 r270
  text "RXD" at 37.87,11.926 h2.2 r270
  text "UART" at 43.89,11.146 h2.4 r270
  text "Segger" at 47.06,10.546 h2.4 r270
  text "Short" at 22.32,1.995 h2.4 r270
  text "Short" at 43.89,1.835 h2.4 r270
  text "SB7" at 10.09,0.715 h2.2 r270
  text "SB6" at 13.22,0.715 h2.2 r270
  text "SB12" at 31.686,0.715 h2.2 r270
  text "SB10" at 34.816,0.715 h2.2 r270
  text "SB11" at 37.886,0.71 h2.2 r270
  text "SB9" at 41.016,0.71 h2.2 r270
  text "RTS" at 40.99,-6.585 h2.2 r270
  text "CTS" at 34.77,-6.645 h2.2 r270
  text "RXD" at 31.67,-6.685 h2.2 r270
  text "TXD" at 37.87,-6.695 h2.2 r270
  text "LED 1" at 10.09,-7.255 h2.2 r270
  text "LED 0" at 13.22,-7.255 h2.2 r270
  text "UART" at 43.89,-7.485 h2.4 r270
  text "Button 1" at 16.31,-8.125 h2.2 r270
  text "Button 0" at 19.4,-8.125 h2.2 r270
  text "Function" at 22.32,-8.605 h2.4 r270
  text "nRF51" at 25.5,-12.345 h2.4 r270
  text "nRF51" at 47.06,-12.345 h2.4 r270
  text "P0.18" at 13.22,-16.485 h2.2 r270
  text "P0.17" at 16.31,-16.485 h2.2 r270
  text "P0.16" at 19.4,-16.485 h2.2 r270
  text "P0.11" at 31.67,-16.485 h2.2 r270
  text "P0.10" at 34.77,-16.485 h2.2 r270
  text "P0.09" at 37.87,-16.485 h2.2 r270
  text "P0.08" at 40.99,-16.485 h2.2 r270
  text "P0.19" at 10.09,-16.495 h2.2 r270
  text "GPIO" at 22.32,-16.615 h2.4 r270
  text "GPIO" at 43.89,-16.635 h2.4 r270
Mechanical 1:
  the board outline again, w0.152
Mechanical 3:
  lines w0.025: 54.656,-2.605 ccw(c54.656,-4.827) 53.084,-6.399 55.572,-8.886 ccw(c56.439,-8.019) 56.439,-9.246 62.179,-9.246 ; 57.237,-2.631 59.724,-5.119 ccw(c60.592,-4.252) 60.592,-5.478 ; 60.579,-5.478 60.786,-5.478 ccw(c60.786,-4.119) 61.747,-5.08 67.982,1.154 cw(c68.762,0.374) 68.762,1.478 71.649,1.478 72.085,1.041 72.796,1.041 ; 62.179,-9.238 ccw(c62.179,-7.379) 63.494,-8.693 69.596,-2.591
Mechanical 4:
  lines w0.203: 57.015,-7.153 61.524,-7.153 ccw(c61.524,-5.794) 62.485,-6.755 ; 57.023,-7.511 61.514,-7.511 ccw(c61.514,-5.763) 62.75,-6.999 ; 62.475,-6.765 68.707,-0.533 cw(c69.444,-1.27) 69.444,-0.228 70.433,-0.228 ; 62.747,-6.996 68.96,-0.783 cw(c69.438,-1.261) 69.438,-0.585 70.432,-0.585
  text "90ohm differensial impedance" at 47.549,0.737 h1.02
Mechanical 15:
  lines w0.152: 5.563,-20 35.077,-20 35.077,20 5.563,20 5.563,-20
  lines w0.2: 20.811,1.277 ccw(c21.811,1.277) 21.811,0.277 27.811,0.277 ccw(c27.811,1.277) 28.811,1.277 28.811,7.277 ccw(c27.811,7.277) 27.811,8.277 21.811,8.277 ccw(c21.811,7.277) 20.811,7.277 20.811,1.277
